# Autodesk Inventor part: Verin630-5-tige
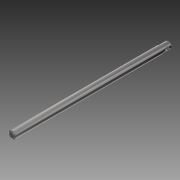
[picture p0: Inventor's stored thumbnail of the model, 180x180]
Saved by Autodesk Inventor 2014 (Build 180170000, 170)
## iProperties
Created: 2015-07
Part Number: Verin630-5-tige
Material: Générique
Document SubType Name: Modeling
Designer: OL
Density: 1 g/cm^3
Appearance: Par défaut
Author: OL
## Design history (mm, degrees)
sketch "Esquisse1"
  geometry: L1 (0, 0)-(616, 0); L2 (0, 0)-(0, 10); L3 (3, 15)-(614.5, 15); L4 (616, 13.5)-(616, 0); L5 (3, 15)-(0, 10); L6 (614.5, 15)-(616, 13.5); L7 (616, 13.5)-(648, 13.5); L8 (648, 13.5)-(650, 11.5); L9 (650, 11.5)-(650, 0); L10 (616, 0)-(650, 0)
  constraints: 20 end point, 5 perpendicular, 2 parallel, 1 horizontal
  dimensions: "d0" = 616 distance of L1.start L1.end; "d1" = 15 distance between parallel lines of L1 L3; "d2" = 3 horizontal distance of L3.start L2.end; "d3" = 5 vertical distance of L3.start L2.end; "d4" = 1.5 horizontal distance of L3.end L4.start; "d5" = 1.5 horizontal distance of L3.end L4.start; "d6" = 34 distance between parallel lines of L4 L9; "d7" = 2 horizontal distance of L7.end L8.end
revolve "Révolution1" sketch "Esquisse1" stored, may be unused: angle "d8" = 90 deg
sketch "Esquisse2"
  geometry: L1 (650, -11.5)-(650, 11.5) reference; C1 r 8.1 at (632, 0); 1 further point
  constraints: 1 centre point
  dimensions: "d9" = 16.2 diameter of C1; "d11" = 18 distance from line of L1 C1.centre; "d12" = 0 vertical distance of C1.centre point (0, 0)
extrude "Extrusion1" cut sketch "Esquisse2" stored distance "d13" = 30; taper "d14" = 0 deg
sketch "Esquisse3"
  geometry: L1 (0, -10)-(0, 10) reference; C1 r 8.25 at (632, 0); 1 further point
  constraints: 1 centre point
  dimensions: "d15" = 632 distance from line of L1 C1.centre; "d16" = 16.5 diameter of C1
extrude "Extrusion2" cut sketch "Esquisse3" stored distance "d17" = 2; taper "d18" = 0 deg
node "Solide1"
